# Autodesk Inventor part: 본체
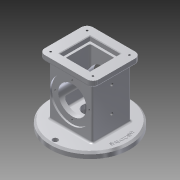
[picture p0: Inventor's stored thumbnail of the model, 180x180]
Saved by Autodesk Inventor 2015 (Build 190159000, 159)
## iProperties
Created: 2019-08
Part Number: 본체
Material: 알루미늄 6061
Document SubType Name: Modeling
Designer: now
Density: 2.7 g/cm^3
Appearance: 알루미늄 - 평지
Mass: 1038.06 g
Surface Area: 785.626 cm^2
Volume: 384.466 cm^3
Author: now
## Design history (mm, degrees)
sketch "스케치1"
  geometry: C1 r 67.5 at (0, 0); 1 further point
  constraints: 1 centre point, 1 coincident
  dimensions: "d0" = 135 diameter of C1
extrude "돌출1" new body sketch "스케치1" distance "d1" = 10; taper "d2" = 0 deg
chamfer "모따기1" distance "d3" = 3; stored, may be unused: second distance "d4" = 2, angle "d5" = 45 deg
sketch "스케치2"
  geometry: C1 r 64.5 at (0, 0) reference; 1 further point
  constraints: 1 horizontal alignment
  dimensions: "d6" = 59 distance of C1.centre point (-59, 0)
hole "구멍1" sketch "스케치2" at (-59, 0) diameter "d7" = 9; stored, may be unused: countersink angle "d11" = 90 deg, drill point angle "d13" = 118 deg; dims "d8" = 6, "d9" = 4, "d10" = 2, "d12" = 8
sketch "스케치4"
  geometry: L1 (37, 33)-(-37, 33); L2 (-37, 33)-(-37, -33); L3 (-37, -33)-(37, -33); L4 (37, -33)-(37, 33); L5 (37, 33)-(-37, -33); L6 (-37, 33)-(37, -33); C1 r 64.5 at (0, 0) reference
  constraints: 12 end point, 2 midpoint, 2 parallel, 1 horizontal, 1 perpendicular
  dimensions: "d23" = 66 distance of L3.end L1.start; "d24" = 74 distance of L1.start L1.end
extrude "돌출3" join sketch "스케치4" distance "d25" = 88; taper "d26" = 0 deg
sketch "스케치5"
  geometry: L1 (46, 41)-(-46, 41); L2 (-46, 41)-(-46, -41); L3 (-46, -41)-(46, -41); L4 (46, -41)-(46, 41); L5 (46, 41)-(-46, -41); L6 (-46, 41)-(46, -41); 1 further point
  constraints: 12 end point, 2 midpoint, 2 parallel, 1 horizontal, 1 perpendicular
  dimensions: "d27" = 82 distance of L3.end L1.start; "d28" = 92 distance of L1.start L1.end
extrude "돌출4" join sketch "스케치5" distance "d29" = 10; taper "d30" = 0 deg
fillet "모깎기1" dims "d31" = 10
fillet "모깎기2" dims "d32" = 3
fillet "모깎기3" dims "d33" = 3
fillet "모깎기4" dims "d34" = 3
fillet "모깎기5" dims "d35" = 3
sketch "스케치6"
  geometry: L1 (-33.5, -13)-(101.5, -13) reference; C1 r 24 at (34, 41); 1 further point
  constraints: 1 centre point, 1 vertical alignment
  dimensions: "d36" = 48 diameter of C1; "d37" = 54 distance from line of L1 C1.centre
extrude "돌출5" cut sketch "스케치6" stored distance "d38" = 10; taper "d39" = 0 deg
sketch "스케치7"
  geometry: C1 r 24 at (34, 41) reference; C2 r 35 at (34, 41); 1 further point
  constraints: 1 centre point, 1 coincident
  dimensions: "d40" = 70 diameter of C2
extrude "돌출6" cut sketch "스케치7" distance "d41" = 3; taper "d42" = 0 deg
sketch "스케치8"
  geometry: L1 (26, 26)-(-26, 26); L2 (-26, 26)-(-26, -26); L3 (-26, -26)-(26, -26); L4 (26, -26)-(26, 26); L5 (26, 26)-(-26, -26); L6 (-26, 26)-(26, -26); 1 further point
  constraints: 12 end point, 2 midpoint, 2 parallel, 1 horizontal, 1 perpendicular
  dimensions: "d43" = 52 distance of L1.end L2.end; "d44" = 52 distance of L1.start L1.end
extrude "돌출7" cut sketch "스케치8" distance "d45" = 8; taper "d46" = 0 deg
sketch "스케치9"
  geometry: L1 (22, -22)-(-22, -22); L2 (-22, -22)-(-22, 22); L3 (-22, 22)-(22, 22); L4 (22, 22)-(22, -22); L5 (22, -22)-(-22, 22); L6 (-22, -22)-(22, 22); 1 further point
  constraints: 12 end point, 2 midpoint, 2 parallel, 1 horizontal, 1 perpendicular
  dimensions: "d47" = 44 distance of L1.end L2.end; "d48" = 44 distance of L2.end L3.end
extrude "돌출8" cut sketch "스케치9" distance "d49" = 74; taper "d50" = 0 deg
sketch "스케치11"
  geometry: C1 r 67.5 at (0, 0) reference; C2 r 25 at (0, 0)
  constraints: 1 centre point, 1 coincident
  dimensions: "d51" = 50 diameter of C2
extrude "돌출9" cut sketch "스케치11" distance "d52" = 18; taper "d53" = 0 deg
sketch "스케치12"
  geometry: C1 r 25 at (0, 0) reference; C2 r 12.5 at (0, 0)
  constraints: 1 centre point, 1 coincident
  dimensions: "d54" = 25 diameter of C2
extrude "돌출10" cut sketch "스케치12" stored distance "d55" = 18; taper "d56" = 0 deg
fillet "모깎기6" dims "d57" = 3
fillet "모깎기7" dims "d58" = 3
fillet "모깎기8" dims "d59" = 3
sketch "스케치13"
  geometry: C1 r 24 at (0, 0) reference; 2 further points
  constraints: 1 vertical alignment
  dimensions: "d60" = 29 distance of C1.centre point (0, 29)
hole "구멍2" sketch "스케치13" at (0, 29) diameter "d61" = 3.242; stored, may be unused: countersink angle "d65" = 90 deg, drill point angle "d67" = 118 deg; dims "d62" = 4, "d63" = 4, "d64" = 2, "d66" = 6
sketch "스케치14"
  geometry: A1 r 10 centre (-36, -31) between (-46, -31) and (-36, -41) reference; A2 r 10 centre (36, -31) between (36, -41) and (46, -31) reference; A3 r 10 centre (36, 31) between (46, 31) and (36, 41) reference; A4 r 10 centre (-36, 31) between (-36, 41) and (-46, 31) reference; 1 further point
hole "구멍3" sketch "스케치14" at (-36, 31), (-36, -31), (36, -31), (36, 31) diameter "d71" = 3.242; stored, may be unused: countersink angle "d75" = 90 deg, drill point angle "d77" = 118 deg; dims "d72" = 4, "d73" = 4, "d74" = 2, "d76" = 6
sketch "스케치15"
  geometry: C1 r 64.5 at (0, 0) reference; C2 r 4.5 at (-59, 0) reference; 1 further point
  constraints: 1 coincident, 1 horizontal alignment, 2 other
feature "엠보싱1" sketch "스케치15" dims "d78" = 0.5, "d79" = 0
chamfer "모따기2" distance "d80" = 1; stored, may be unused: second distance "d81" = 2, angle "d82" = 45 deg
sketch "스케치16"
  geometry: L1 (13, -37.5)-(13, 97.5) reference; 3 further points
  constraints: 2 horizontal alignment
  dimensions: "d83" = 37 distance from line of L1 point (-24, 30); "d84" = 43 distance of point (-24, 30) point (-67, 30)
hole "구멍4" sketch "스케치16" at (-67, 30), (-24, 30) diameter "d85" = 4.917; stored, may be unused: countersink angle "d89" = 90 deg, drill point angle "d91" = 118 deg; dims "d86" = 12, "d87" = 4, "d88" = 2, "d90" = 15
fillet "모깎기9" dims "d92" = 3
node "솔리드1"
pattern_circular "원형 패턴1" dims angle "d15" = 90 deg
mirror "대칭1"
mirror "대칭2"
pattern_circular "원형 패턴2" dims angle "d69" = 360 deg
mirror "대칭3"
